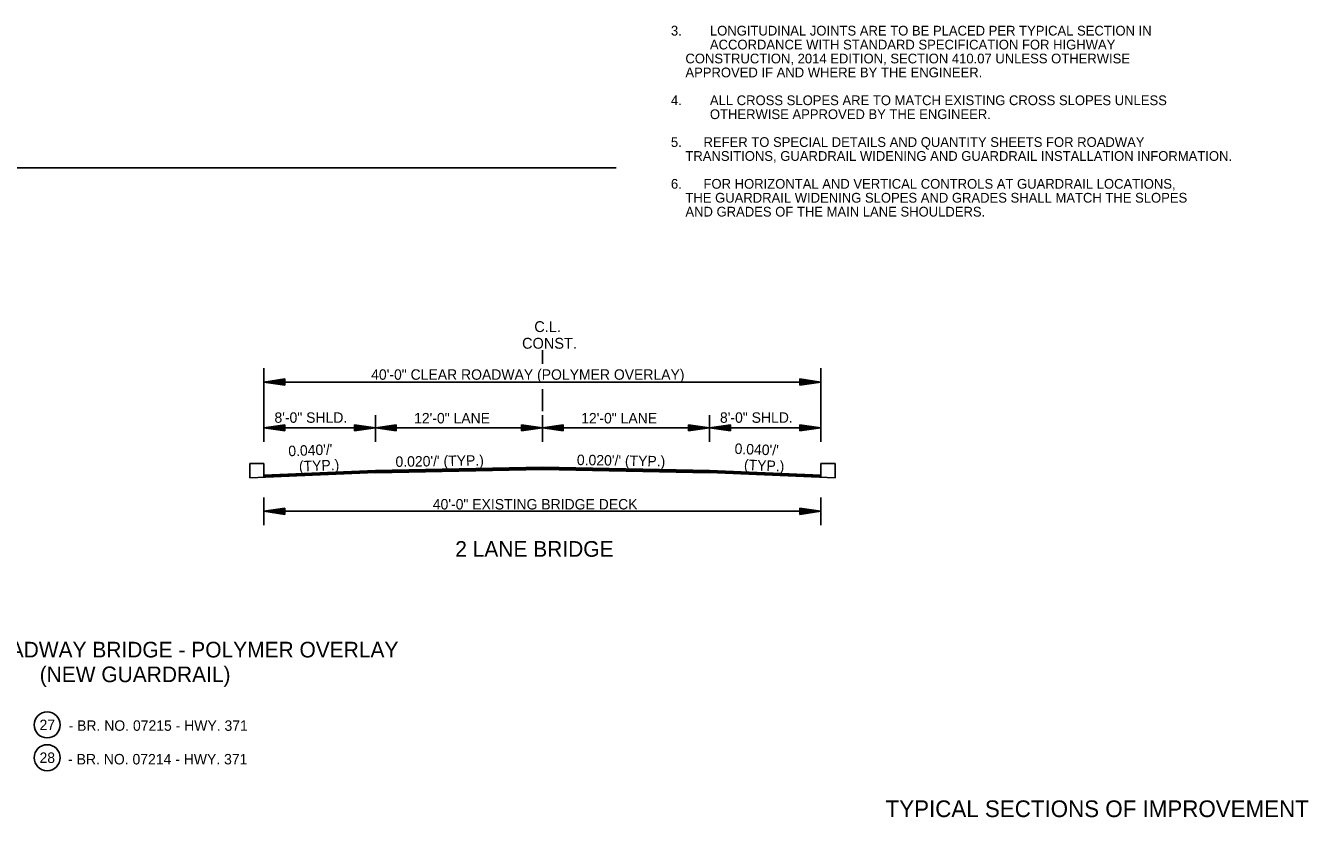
# Model space of a CAD drawing. Extents: x 545241 to 1930787, y -1971772 to 596640.
# Drawn here: x 547347 to 548268, y -1960072 to -1959503 of the extents above; entities that cross this region are included whole.
import ezdxf

# ---------------------------------------------------------------- set-up
doc = ezdxf.new("R2010")
doc.units = 0
for name, color, linetype in [('R_Border', 7, 'Continuous'), ('R_Border Notes', 7, 'Continuous'), ('R_Draft', 7, 'Continuous')]:
    doc.layers.add(name, color=color, linetype=linetype)

msp = doc.modelspace()

# ---------------------------------------------------------------- linework, layer by layer
at = {"layer": 'R_Border'}
for p, q in [((546742.77, -1959605.24), (547770.72, -1959605.24)), ((547507.54, -1959817.74), (547507.53, -1959827.85)), ((547517.71, -1959817.74), (547507.54, -1959817.74)), ((547517.71, -1959827.15), (547517.71, -1959817.74)), ((547917.71, -1959817.74), (547927.88, -1959817.74)), ((547917.71, -1959827.15), (547917.71, -1959817.74)), ((547927.88, -1959817.74), (547927.89, -1959827.85))]:
    msp.add_line(p, q, dxfattribs=at)
for centre in [(547361.97, -1960005.41), (547361.97, -1960028.98)]:
    msp.add_circle(centre, 9.34, dxfattribs=at)
at = {"layer": 'R_Draft'}
for p, q in [((547717.71, -1959746.16), (547717.71, -1959736.16)), ((547517.71, -1959802.04), (547517.71, -1959749.31)), ((547917.71, -1959802.04), (547917.71, -1959749.31)), ((547532.71, -1959756.95), (547517.71, -1959759.2)), ((547917.71, -1959759.2), (547517.71, -1959759.2)), ((547532.71, -1959761.45), (547517.71, -1959759.2)), ((547532.71, -1959757.33), (547520.22, -1959759.2)), ((547532.71, -1959761.08), (547520.22, -1959759.2)), ((547532.71, -1959757.71), (547522.8, -1959759.2)), ((547532.71, -1959760.7), (547522.8, -1959759.2)), ((547532.71, -1959758.09), (547525.29, -1959759.2)), ((547532.71, -1959760.32), (547525.29, -1959759.2)), ((547532.71, -1959758.48), (547527.84, -1959759.2)), ((547532.71, -1959759.94), (547527.84, -1959759.2)), ((547532.71, -1959758.85), (547530.34, -1959759.2)), ((547532.71, -1959759.56), (547530.34, -1959759.2)), ((547532.71, -1959756.95), (547532.71, -1959761.45)), ((547887.71, -1959759.2), (547607.71, -1959759.2)), ((547902.71, -1959756.95), (547917.71, -1959759.2)), ((547902.71, -1959761.45), (547902.71, -1959756.95)), ((547902.71, -1959757.33), (547915.21, -1959759.2)), ((547902.71, -1959757.71), (547912.63, -1959759.2)), ((547902.71, -1959758.09), (547910.13, -1959759.2)), ((547902.71, -1959758.47), (547907.59, -1959759.2)), ((547902.71, -1959758.85), (547905.08, -1959759.2)), ((547902.71, -1959761.45), (547917.71, -1959759.2)), ((547902.71, -1959759.93), (547907.59, -1959759.2)), ((547902.71, -1959760.7), (547912.63, -1959759.2)), ((547902.71, -1959761.08), (547915.21, -1959759.2)), ((547902.71, -1959760.32), (547910.13, -1959759.2)), ((547902.71, -1959759.56), (547905.08, -1959759.2)), ((547717.71, -1959780.02), (547717.71, -1959764.32)), ((547532.71, -1959789.79), (547517.71, -1959792.04)), ((547532.71, -1959790.16), (547520.22, -1959792.04)), ((547532.71, -1959789.79), (547532.71, -1959794.29)), ((547582.71, -1959789.79), (547597.71, -1959792.04)), ((547582.71, -1959789.79), (547582.71, -1959794.29)), ((547582.71, -1959790.16), (547595.21, -1959792.04)), ((547597.71, -1959802.04), (547597.71, -1959782.85)), ((547612.71, -1959789.79), (547597.71, -1959792.04)), ((547612.71, -1959790.16), (547600.22, -1959792.04)), ((547612.71, -1959789.79), (547612.71, -1959794.29)), ((547702.71, -1959789.79), (547717.71, -1959792.04)), ((547702.71, -1959789.79), (547702.71, -1959794.29)), ((547702.71, -1959790.16), (547715.21, -1959792.04)), ((547717.71, -1959802.04), (547717.71, -1959782.85)), ((547732.71, -1959789.79), (547717.71, -1959792.04)), ((547732.71, -1959790.16), (547720.22, -1959792.04)), ((547732.71, -1959789.79), (547732.71, -1959794.29)), ((547822.71, -1959789.79), (547837.71, -1959792.04)), ((547822.71, -1959789.79), (547822.71, -1959794.29)), ((547822.71, -1959790.16), (547835.21, -1959792.04)), ((547837.71, -1959802.04), (547837.71, -1959782.85)), ((547852.71, -1959789.79), (547837.71, -1959792.04)), ((547852.71, -1959790.16), (547840.22, -1959792.04)), ((547852.71, -1959789.79), (547852.71, -1959794.29)), ((547902.71, -1959789.79), (547917.71, -1959792.04)), ((547902.71, -1959789.79), (547902.71, -1959794.29)), ((547902.71, -1959790.16), (547915.21, -1959792.04)), ((547597.71, -1959792.04), (547517.71, -1959792.04)), ((547532.71, -1959794.29), (547517.71, -1959792.04)), ((547532.71, -1959793.91), (547520.22, -1959792.04)), ((547532.71, -1959790.54), (547522.8, -1959792.04)), ((547532.71, -1959793.53), (547522.8, -1959792.04)), ((547532.71, -1959790.92), (547525.29, -1959792.04)), ((547532.71, -1959793.15), (547525.29, -1959792.04)), ((547532.71, -1959791.31), (547527.84, -1959792.04)), ((547532.71, -1959792.77), (547527.84, -1959792.04)), ((547532.71, -1959791.68), (547530.34, -1959792.04)), ((547532.71, -1959792.39), (547530.34, -1959792.04)), ((547582.71, -1959790.54), (547592.63, -1959792.04)), ((547582.71, -1959790.92), (547590.13, -1959792.04)), ((547582.71, -1959791.31), (547587.59, -1959792.04)), ((547582.71, -1959791.68), (547585.08, -1959792.04)), ((547582.71, -1959794.29), (547597.71, -1959792.04)), ((547582.71, -1959792.77), (547587.59, -1959792.04)), ((547582.71, -1959793.53), (547592.63, -1959792.04)), ((547582.71, -1959793.91), (547595.21, -1959792.04)), ((547582.71, -1959793.15), (547590.13, -1959792.04)), ((547582.71, -1959792.39), (547585.08, -1959792.04)), ((547717.71, -1959792.04), (547597.71, -1959792.04)), ((547612.71, -1959794.29), (547597.71, -1959792.04)), ((547612.71, -1959793.91), (547600.22, -1959792.04)), ((547612.71, -1959790.54), (547602.8, -1959792.04)), ((547612.71, -1959793.53), (547602.8, -1959792.04)), ((547612.71, -1959790.92), (547605.29, -1959792.04)), ((547612.71, -1959793.15), (547605.29, -1959792.04)), ((547612.71, -1959791.31), (547607.84, -1959792.04)), ((547612.71, -1959792.77), (547607.84, -1959792.04)), ((547612.71, -1959791.68), (547610.34, -1959792.04)), ((547612.71, -1959792.39), (547610.34, -1959792.04)), ((547702.71, -1959790.54), (547712.63, -1959792.04)), ((547702.71, -1959790.92), (547710.13, -1959792.04)), ((547702.71, -1959791.31), (547707.59, -1959792.04)), ((547702.71, -1959791.68), (547705.08, -1959792.04)), ((547702.71, -1959794.29), (547717.71, -1959792.04)), ((547702.71, -1959792.77), (547707.59, -1959792.04)), ((547702.71, -1959793.53), (547712.63, -1959792.04)), ((547702.71, -1959793.91), (547715.21, -1959792.04)), ((547702.71, -1959793.15), (547710.13, -1959792.04)), ((547702.71, -1959792.39), (547705.08, -1959792.04)), ((547837.71, -1959792.04), (547717.71, -1959792.04)), ((547732.71, -1959794.29), (547717.71, -1959792.04)), ((547732.71, -1959793.91), (547720.22, -1959792.04)), ((547732.71, -1959790.54), (547722.8, -1959792.04)), ((547732.71, -1959793.53), (547722.8, -1959792.04)), ((547732.71, -1959790.92), (547725.29, -1959792.04)), ((547732.71, -1959793.15), (547725.29, -1959792.04)), ((547732.71, -1959791.31), (547727.84, -1959792.04)), ((547732.71, -1959792.77), (547727.84, -1959792.04)), ((547732.71, -1959791.68), (547730.34, -1959792.04)), ((547732.71, -1959792.39), (547730.34, -1959792.04)), ((547822.71, -1959790.54), (547832.63, -1959792.04)), ((547822.71, -1959790.92), (547830.13, -1959792.04)), ((547822.71, -1959791.31), (547827.59, -1959792.04)), ((547822.71, -1959791.68), (547825.08, -1959792.04)), ((547822.71, -1959794.29), (547837.71, -1959792.04)), ((547822.71, -1959792.77), (547827.59, -1959792.04)), ((547822.71, -1959793.53), (547832.63, -1959792.04)), ((547822.71, -1959793.91), (547835.21, -1959792.04)), ((547822.71, -1959793.15), (547830.13, -1959792.04)), ((547822.71, -1959792.39), (547825.08, -1959792.04)), ((547837.71, -1959792.04), (547917.71, -1959792.04)), ((547852.71, -1959794.29), (547837.71, -1959792.04)), ((547852.71, -1959793.91), (547840.22, -1959792.04)), ((547852.71, -1959790.54), (547842.8, -1959792.04)), ((547852.71, -1959793.53), (547842.8, -1959792.04)), ((547852.71, -1959790.92), (547845.29, -1959792.04)), ((547852.71, -1959793.15), (547845.29, -1959792.04)), ((547852.71, -1959791.31), (547847.84, -1959792.04)), ((547852.71, -1959792.77), (547847.84, -1959792.04)), ((547852.71, -1959791.68), (547850.34, -1959792.04)), ((547852.71, -1959792.39), (547850.34, -1959792.04)), ((547902.71, -1959790.54), (547912.63, -1959792.04)), ((547902.71, -1959790.92), (547910.13, -1959792.04)), ((547902.71, -1959791.31), (547907.59, -1959792.04)), ((547902.71, -1959791.68), (547905.08, -1959792.04)), ((547902.71, -1959794.29), (547917.71, -1959792.04)), ((547902.71, -1959792.77), (547907.59, -1959792.04)), ((547902.71, -1959793.53), (547912.63, -1959792.04)), ((547902.71, -1959793.91), (547915.21, -1959792.04)), ((547902.71, -1959793.15), (547910.13, -1959792.04)), ((547902.71, -1959792.39), (547905.08, -1959792.04)), ((547597.71, -1959824.25), (547507.53, -1959827.85)), ((547597.71, -1959822.75), (547517.71, -1959825.95)), ((547597.71, -1959823.05), (547517.71, -1959826.25)), ((547597.71, -1959823.35), (547517.71, -1959826.55)), ((547597.71, -1959823.65), (547517.71, -1959826.85)), ((547597.71, -1959823.95), (547517.71, -1959827.15)), ((547717.71, -1959820.35), (547597.71, -1959822.75)), ((547717.71, -1959820.65), (547597.71, -1959823.05)), ((547717.71, -1959820.95), (547597.71, -1959823.35)), ((547717.71, -1959821.25), (547597.71, -1959823.65)), ((547717.71, -1959821.55), (547597.71, -1959823.95)), ((547717.71, -1959821.85), (547597.71, -1959824.25)), ((547717.71, -1959822.02), (547597.71, -1959824.42)), ((547717.71, -1959820.35), (547837.71, -1959822.75)), ((547717.71, -1959820.65), (547837.71, -1959823.05)), ((547717.71, -1959820.95), (547837.71, -1959823.35)), ((547717.71, -1959821.25), (547837.71, -1959823.65)), ((547717.71, -1959821.55), (547837.71, -1959823.95)), ((547717.71, -1959821.85), (547837.71, -1959824.25)), ((547717.71, -1959822.02), (547837.71, -1959824.42)), ((547837.71, -1959822.75), (547917.71, -1959825.95)), ((547837.71, -1959823.05), (547917.71, -1959826.25)), ((547837.71, -1959823.35), (547917.71, -1959826.55)), ((547837.71, -1959823.65), (547917.71, -1959826.85)), ((547837.71, -1959823.95), (547917.71, -1959827.15)), ((547837.71, -1959824.25), (547927.88, -1959827.85)), ((547517.71, -1959842.01), (547517.71, -1959862.01)), ((547917.71, -1959842.01), (547917.71, -1959862.01)), ((547532.71, -1959849.76), (547517.71, -1959852.01)), ((547532.71, -1959854.26), (547517.71, -1959852.01)), ((547917.71, -1959852.01), (547517.71, -1959852.01)), ((547532.71, -1959850.13), (547520.22, -1959852.01)), ((547532.71, -1959853.88), (547520.22, -1959852.01)), ((547532.71, -1959850.51), (547522.8, -1959852.01)), ((547532.71, -1959853.5), (547522.8, -1959852.01)), ((547532.71, -1959850.89), (547525.29, -1959852.01)), ((547532.71, -1959853.12), (547525.29, -1959852.01)), ((547532.71, -1959851.28), (547527.84, -1959852.01)), ((547532.71, -1959852.74), (547527.84, -1959852.01)), ((547532.71, -1959851.65), (547530.34, -1959852.01)), ((547532.71, -1959852.36), (547530.34, -1959852.01)), ((547532.71, -1959849.76), (547532.71, -1959854.26)), ((547902.71, -1959849.76), (547917.71, -1959852.01)), ((547902.71, -1959854.26), (547902.71, -1959849.76)), ((547902.71, -1959850.13), (547915.21, -1959852.01)), ((547902.71, -1959850.51), (547912.63, -1959852.01)), ((547902.71, -1959850.89), (547910.13, -1959852.01)), ((547902.71, -1959851.27), (547907.59, -1959852.01)), ((547902.71, -1959851.65), (547905.08, -1959852.01)), ((547902.71, -1959854.26), (547917.71, -1959852.01)), ((547902.71, -1959852.73), (547907.59, -1959852.01)), ((547902.71, -1959853.5), (547912.63, -1959852.01)), ((547902.71, -1959853.88), (547915.21, -1959852.01)), ((547902.71, -1959853.12), (547910.13, -1959852.01)), ((547902.71, -1959852.36), (547905.08, -1959852.01))]:
    msp.add_line(p, q, dxfattribs=at)

# ---------------------------------------------------------------- texts
at = {"layer": 'R_Border'}
msp.add_text('(NEW GUARDRAIL)', height=11.25, dxfattribs=at).set_placement((547356.59, -1959974.72))
msp.add_text('TYPICAL SECTIONS OF IMPROVEMENT', height=12, rotation=360, dxfattribs=at).set_placement((547964.19, -1960071.64))
at = {"layer": 'R_Border Notes'}
for s, p in [('3.', (547810.01, -1959510.31)), ('LONGITUDINAL JOINTS ARE TO BE PLACED PER TYPICAL SECTION IN ', (547838.01, -1959510.31)), ('ACCORDANCE WITH STANDARD SPECIFICATION FOR HIGHWAY', (547838.01, -1959520.31)), ('    CONSTRUCTION, 2014 EDITION, SECTION 410.07 UNLESS OTHERWISE', (547810.01, -1959530.31)), ('    APPROVED IF AND WHERE BY THE ENGINEER.', (547810.01, -1959540.31)), ('4.', (547810.01, -1959560.31)), ('ALL CROSS SLOPES ARE TO MATCH EXISTING CROSS SLOPES UNLESS ', (547838.01, -1959560.31)), ('OTHERWISE APPROVED BY THE ENGINEER.', (547838.01, -1959570.31)), ('5.      REFER TO SPECIAL DETAILS AND QUANTITY SHEETS FOR ROADWAY', (547810.01, -1959590.31)), ('    TRANSITIONS, GUARDRAIL WIDENING AND GUARDRAIL INSTALLATION INFORMATION.', (547810.01, -1959600.31)), ('6.      FOR HORIZONTAL AND VERTICAL CONTROLS AT GUARDRAIL LOCATIONS,', (547810.01, -1959620.31)), ('    THE GUARDRAIL WIDENING SLOPES AND GRADES SHALL MATCH THE SLOPES', (547810.01, -1959630.31)), ('    AND GRADES OF THE MAIN LANE SHOULDERS. ', (547810.01, -1959640.31))]:
    msp.add_text(s, height=7, dxfattribs=at).set_placement(p)
at = {"layer": 'R_Draft'}
for s, height, p in [('C.L.', 7.8, (547711.87, -1959723.27)), ('CONST.', 7.8, (547703.08, -1959735.23)), ('40\'-0" CLEAR ROADWAY (POLYMER OVERLAY)', 7.5, (547594.68, -1959757.53)), ('8\'-0" SHLD.', 7.5, (547525.23, -1959788.43)), ('12\'-0" LANE', 7.5, (547625.53, -1959788.87)), ('12\'-0" LANE', 7.5, (547745.53, -1959788.87)), ('8\'-0" SHLD.', 7.5, (547845.23, -1959788.43)), ('40\'-0" EXISTING BRIDGE DECK', 7.5, (547638.97, -1959850.68)), ('2 LANE BRIDGE', 11.25, (547655.08, -1959884.65)), ('40 FT. CLEAR ROADWAY BRIDGE - POLYMER OVERLAY', 11.25, (547210.51, -1959956.98)), ('27', 7.5, (547356.48, -1960009.16)), ('- BR. NO. 07215 - HWY. 371', 7.5, (547377.34, -1960009.66)), ('28', 7.5, (547356.48, -1960032.73)), ('- BR. NO. 07214 - HWY. 371', 7.5, (547377.02, -1960033.79))]:
    msp.add_text(s, height=height, dxfattribs=at).set_placement(p)
for s, rotation, p in [("0.040'/'", 2.29061, (547535.32, -1959812.49)), ("0.040'/'", 357.70939, (547855.62, -1959810.71)), ('(TYP.)', 2.29061, (547542.96, -1959823.44)), ("0.020'/' (TYP.)", 0.97192, (547612.23, -1959820.14)), ("0.020'/' (TYP.)", 359.02808, (547742.41, -1959818.77)), ('(TYP.)', 357.70939, (547862.36, -1959822.24))]:
    msp.add_text(s, height=7.5, rotation=rotation, dxfattribs=at).set_placement(p)

doc.saveas('drawing.dxf')
